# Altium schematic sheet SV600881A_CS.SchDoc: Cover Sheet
size 431 x 279 mm; Date: Not shown in title block; ApprovedBy: Not shown in title block; CheckedBy: Not shown in title block; Author: Not shown in title block; CompanyName: Not shown in title block; DrawnBy: KNielson; Engineer: Eric Lee; Organization: Not shown in title block; Address1: Not shown in title block; Address2: Not shown in title block; Address3: Not shown in title block; Address4: Not shown in title block; DocumentNumber: 1; Revision: Use project parameter SCH_Rev; SheetNumber: 1; SheetTotal: 4; PageSetup: Record=PageOptions¦CenterHorizontal=True¦CenterVertical=True¦PrintScale=1.00¦XCorrection=1.00¦YCorrection=1.00¦PrintKind=0¦BorderSize=5000000¦LeftOffset=0¦BottomOffset=0¦Orientation=2¦PaperLength=1000¦PaperWidth=1000¦Scale=100¦PaperSource=15¦PrintQuality=600¦MediaType=1¦DitherType=10¦PaperKind=Letter¦PrintScaleMode=1
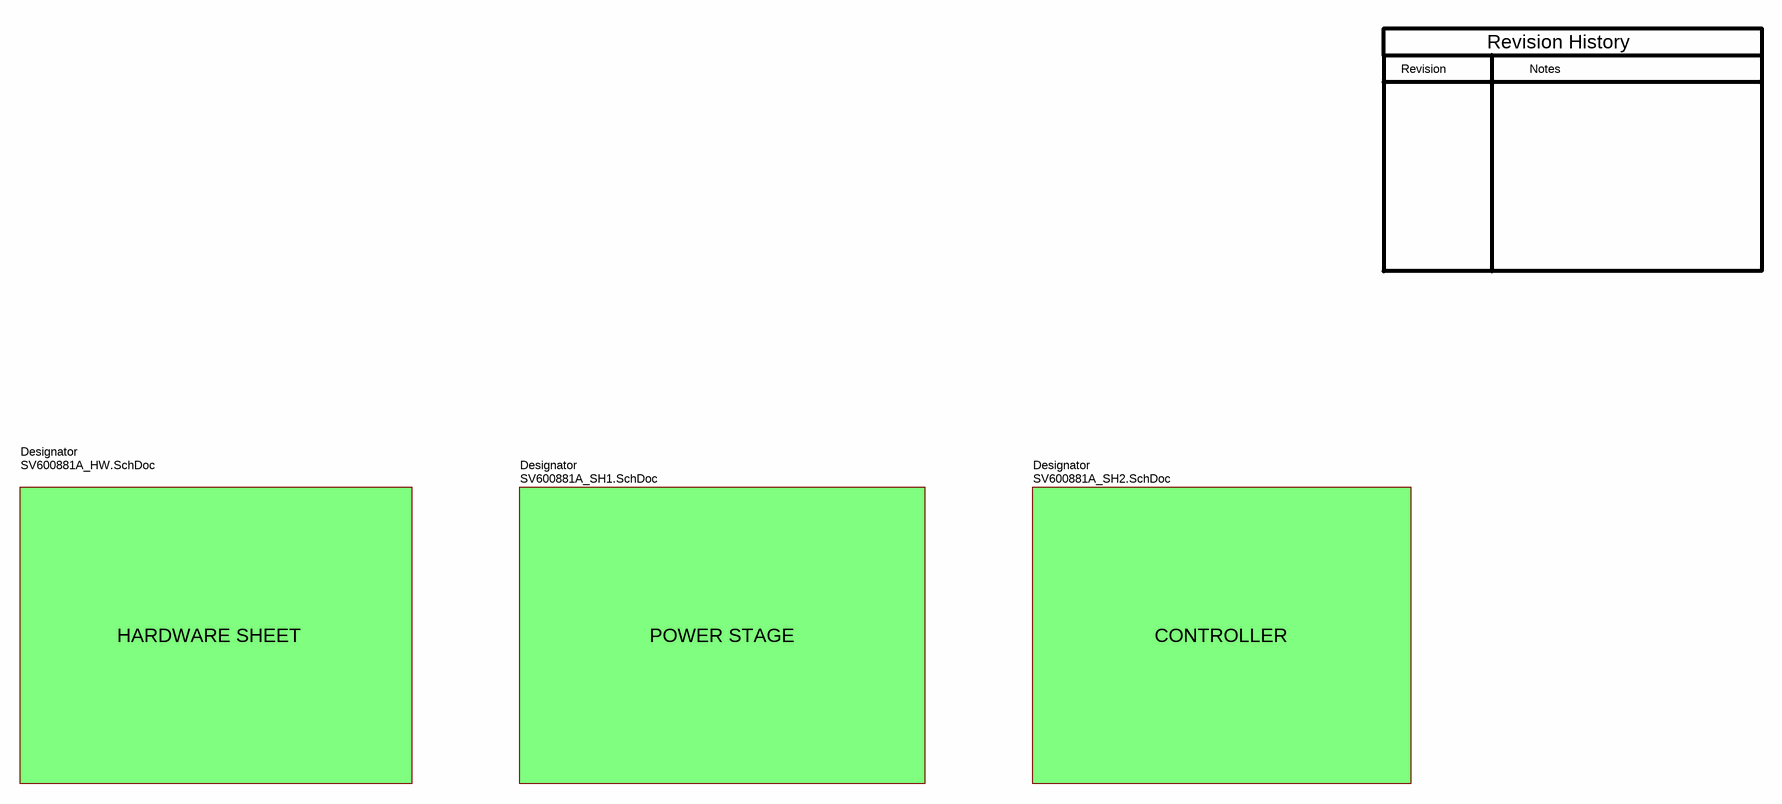
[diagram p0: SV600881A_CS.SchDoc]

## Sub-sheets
Designator = SV600881A_HW.SchDoc: no entries
Designator = SV600881A_SH1.SchDoc: no entries
Designator = SV600881A_SH2.SchDoc: no entries

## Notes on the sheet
- Revision
- Notes
- Revision History
- HARDWARE SHEET
- POWER STAGE
- CONTROLLER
